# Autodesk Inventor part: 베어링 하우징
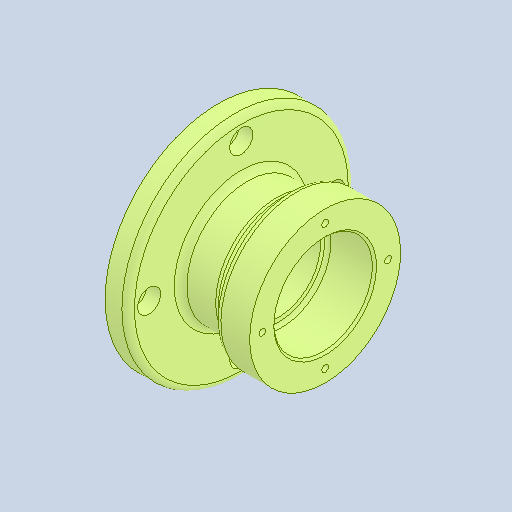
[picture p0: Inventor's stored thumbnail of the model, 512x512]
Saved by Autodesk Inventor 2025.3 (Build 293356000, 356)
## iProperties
Created: 2026-01
Part Number: 베어링 하우징
Material: 알루미늄 6061
Document SubType Name: Modeling
Designer: PC-13
Density: 2.7 g/cm^3
Appearance: 기본값
Author: jhkim
Sending System: Autodesk Inventor 2026
Preprocessor: ST-DEVELOPER v20.1
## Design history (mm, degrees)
feature "솔리드1"
node "솔리드2"
